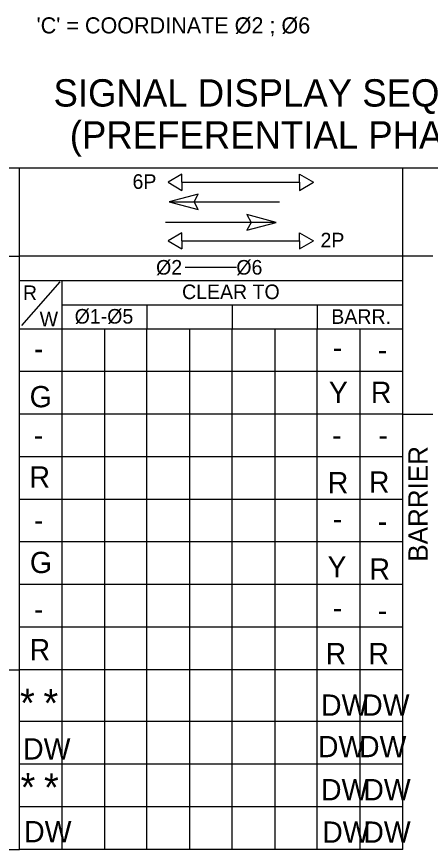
# Model space of a CAD drawing. Extents: x 0 to 3.01, y -0.05 to 1.83.
# Drawn here: x 2.5103 to 2.6475, y 1.2634 to 1.5395 of the extents above; entities that cross this region are included whole.
import ezdxf

# ---------------------------------------------------------------- set-up
doc = ezdxf.new("R2010")
doc.units = 0
for name, color, linetype in [('TR_TS_Border', 7, 'Continuous'), ('TR_TS_Phase1', 7, 'Continuous'), ('TR_TS_Phase2', 7, 'Continuous'), ('TR_TS_Phase3', 7, 'Continuous'), ('TR_TS_Phase4', 7, 'Continuous'), ('TR_TS_Phase5', 7, 'Continuous'), ('TR_TS_Phase6', 7, 'Continuous'), ('TR_TS_Phase7', 7, 'Continuous'), ('TR_TS_Phase8', 7, 'Continuous')]:
    doc.layers.add(name, color=color, linetype=linetype)

msp = doc.modelspace()

# ---------------------------------------------------------------- linework, layer by layer
at = {"layer": 'TR_TS_Border'}
for p, q in [((2.9074756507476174, 1.4891940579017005), (2.2983729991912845, 1.4891940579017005)), ((2.511179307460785, 1.4891941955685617), (2.511179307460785, 1.2634424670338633)), ((2.638251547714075, 1.4891941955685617), (2.638251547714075, 1.4077126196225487)), ((2.565108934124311, 1.467816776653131), (2.5605186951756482, 1.4651515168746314)), ((2.565108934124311, 1.4651515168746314), (2.565108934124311, 1.467816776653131)), ((2.604115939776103, 1.4651515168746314), (2.604115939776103, 1.467816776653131)), ((2.604115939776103, 1.467816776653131), (2.60870600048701, 1.4651515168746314)), ((2.5605186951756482, 1.4651515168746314), (2.565108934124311, 1.4624862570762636)), ((2.565108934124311, 1.4651515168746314), (2.565108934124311, 1.4624862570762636)), ((2.565108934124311, 1.4651515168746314), (2.604002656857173, 1.4651515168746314)), ((2.604115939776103, 1.4651515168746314), (2.604115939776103, 1.4624862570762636)), ((2.604115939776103, 1.4624862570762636), (2.60870600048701, 1.4651515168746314)), ((2.506117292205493, 1.4601230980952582), (2.511179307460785, 1.4601230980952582)), ((2.638251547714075, 1.4601230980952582), (2.511179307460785, 1.4601230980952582)), ((2.6483222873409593, 1.4601230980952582), (2.638251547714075, 1.4601230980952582)), ((2.566202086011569, 1.4563796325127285), (2.583186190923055, 1.4563796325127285)), ((2.511179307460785, 1.4520558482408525), (2.638251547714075, 1.4520558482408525)), ((2.5253103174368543, 1.4520558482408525), (2.5253103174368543, 1.2634424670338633)), ((2.512022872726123, 1.4371341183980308), (2.5246774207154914, 1.4515814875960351)), ((2.5253103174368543, 1.4439888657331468), (2.638251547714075, 1.4439888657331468)), ((2.5535190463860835, 1.4439888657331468), (2.5535190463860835, 1.4359214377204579)), ((2.5817279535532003, 1.4439888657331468), (2.5817279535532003, 1.4359214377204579)), ((2.609989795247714, 1.4439888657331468), (2.609989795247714, 1.4359214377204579)), ((2.638251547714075, 1.4359214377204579), (2.511179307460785, 1.4359214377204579)), ((2.5393882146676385, 1.4359214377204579), (2.5393882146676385, 1.2634424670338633)), ((2.5535190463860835, 1.2634424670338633), (2.5535190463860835, 1.4359214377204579)), ((2.567650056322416, 1.4359214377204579), (2.567650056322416, 1.2634424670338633)), ((2.5817279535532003, 1.2634424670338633), (2.5817279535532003, 1.4359214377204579)), ((2.595858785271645, 1.4359214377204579), (2.595858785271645, 1.2634424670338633)), ((2.609989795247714, 1.2634424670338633), (2.609989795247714, 1.4359214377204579)), ((2.6241206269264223, 1.4359214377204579), (2.6241206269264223, 1.2634424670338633)), ((2.638251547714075, 1.4217904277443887), (2.511179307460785, 1.4217904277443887)), ((2.638251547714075, 1.4077126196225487), (2.511179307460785, 1.4077126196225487)), ((2.638251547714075, 1.4077126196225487), (2.638251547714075, 1.2634424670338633)), ((2.638251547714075, 1.4077126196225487), (2.6483222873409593, 1.4077126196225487)), ((2.638251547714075, 1.39358169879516), (2.511179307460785, 1.39358169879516)), ((2.638251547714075, 1.3794506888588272), (2.511179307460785, 1.3794506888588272)), ((2.638251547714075, 1.365372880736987), (2.511179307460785, 1.365372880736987)), ((2.638251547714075, 1.3512419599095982), (2.511179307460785, 1.3512419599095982)), ((2.638251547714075, 1.3371109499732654), (2.511179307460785, 1.3371109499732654)), ((2.506117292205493, 1.3229801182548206), (2.511179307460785, 1.3229801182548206)), ((2.638251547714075, 1.3229801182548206), (2.511179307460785, 1.3229801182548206)), ((2.638324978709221, 1.3058350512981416), (2.5112527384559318, 1.3058350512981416)), ((2.638324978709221, 1.2917041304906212), (2.5112527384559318, 1.2917041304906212)), ((2.638324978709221, 1.2775732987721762), (2.5112527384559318, 1.2775732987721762)), ((2.5061908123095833, 1.2634424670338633), (2.5112527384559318, 1.2634424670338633)), ((2.638324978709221, 1.2634424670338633), (2.5112527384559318, 1.2634424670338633))]:
    msp.add_line(p, q, dxfattribs=at)
at = {"layer": 'TR_TS_Phase2'}
for p, q in [((2.5963022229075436, 1.4712633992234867), (2.5596551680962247, 1.4712633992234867)), ((2.5866775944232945, 1.4738546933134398), (2.5880103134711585, 1.4712633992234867)), ((2.5963022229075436, 1.4712633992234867), (2.5866775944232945, 1.4738546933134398)), ((2.5880103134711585, 1.4712633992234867), (2.5866775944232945, 1.4686721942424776)), ((2.5866775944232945, 1.4686721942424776), (2.5963022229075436, 1.4712633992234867))]:
    msp.add_line(p, q, dxfattribs=at)
at = {"layer": 'TR_TS_Phase6'}
for p, q in [((2.565108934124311, 1.4872207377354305), (2.5605186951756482, 1.4845554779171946)), ((2.565108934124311, 1.4845554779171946), (2.565108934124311, 1.4872207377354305)), ((2.604115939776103, 1.4872207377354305), (2.60870600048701, 1.4845554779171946)), ((2.604115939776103, 1.4845554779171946), (2.604115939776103, 1.4872207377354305)), ((2.5605186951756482, 1.4845554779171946), (2.565108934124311, 1.4818902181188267)), ((2.565108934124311, 1.4845554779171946), (2.565108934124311, 1.4818902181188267)), ((2.565108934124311, 1.4845554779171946), (2.604115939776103, 1.4845554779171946)), ((2.604115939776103, 1.4818902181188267), (2.60870600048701, 1.4845554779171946)), ((2.604115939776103, 1.4845554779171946), (2.604115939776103, 1.4818902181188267)), ((2.570465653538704, 1.4806770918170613), (2.5608412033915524, 1.4780859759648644)), ((2.569132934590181, 1.4780859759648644), (2.570465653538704, 1.4806770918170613)), ((2.5608412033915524, 1.4780859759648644), (2.5974881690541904, 1.4780859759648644)), ((2.5608412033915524, 1.4780859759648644), (2.570465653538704, 1.4754946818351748)), ((2.570465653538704, 1.4754946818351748), (2.569132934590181, 1.4780859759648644))]:
    msp.add_line(p, q, dxfattribs=at)

# ---------------------------------------------------------------- texts
at = {"layer": 'TR_TS_Border'}
for s, height, p in [("'C' = COORDINATE Ø2 ; Ø6", 0.0053469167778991, (2.5169014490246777, 1.5339009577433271)), ('SIGNAL DISPLAY SEQUENCE', 0.00906283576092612, (2.522526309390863, 1.5096612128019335)), ('(PREFERENTIAL PHASING)', 0.00906283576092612, (2.527912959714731, 1.4957467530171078)), ('2P', 0.004840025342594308, (2.611054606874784, 1.462976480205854))]:
    msp.add_text(s, height=height, dxfattribs=at).set_placement(p)
for s, height, rotation, p in [('Ø2          Ø6', 0.0048400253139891, 360, (2.556538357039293, 1.4539533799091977)), ('R', 0.004840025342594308, 360, (2.5123772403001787, 1.445516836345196)), ('CLEAR TO', 0.004840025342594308, 360, (2.565147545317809, 1.445833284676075)), ('W', 0.004840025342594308, 360, (2.517924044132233, 1.4368168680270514)), ('Ø1-Ø5', 0.004840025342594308, 360, (2.5295400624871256, 1.4377132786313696)), ('BARR.', 0.004840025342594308, 360, (2.6146445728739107, 1.4376254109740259)), ('BARRIER', 0.006449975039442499, 89.99999722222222, (2.6466355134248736, 1.3587942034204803))]:
    msp.add_text(s, height=height, rotation=rotation, dxfattribs=at).set_placement(p)
at = {"layer": 'TR_TS_Phase1'}
for p in [(2.516020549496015, 1.4259156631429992), (2.615139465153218, 1.4263307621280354), (2.630069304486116, 1.4255008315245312)]:
    msp.add_text('-', height=0.007050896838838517, dxfattribs=at).set_placement(p)
at = {"layer": 'TR_TS_Phase2'}
for s, p in [('G', (2.5146087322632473, 1.4099803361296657)), ('Y', (2.6138253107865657, 1.4114134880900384)), ('R', (2.6277444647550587, 1.4114134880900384))]:
    msp.add_text(s, height=0.007050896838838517, rotation=360, dxfattribs=at).set_placement(p)
for s, height, p in [('*', 0.009384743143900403, (2.511423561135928, 1.307294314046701)), ('*', 0.009384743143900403, (2.519194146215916, 1.3072379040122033)), ('DW', 0.007050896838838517, (2.6112267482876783, 1.307732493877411)), ('DW', 0.007050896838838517, (2.6248564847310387, 1.3077502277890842))]:
    msp.add_text(s, height=height, dxfattribs=at).set_placement(p)
at = {"layer": 'TR_TS_Phase3'}
for p in [(2.516010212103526, 1.3972038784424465), (2.6149433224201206, 1.3972038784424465), (2.630282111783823, 1.3972038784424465)]:
    msp.add_text('-', height=0.007050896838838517, dxfattribs=at).set_placement(p)
at = {"layer": 'TR_TS_Phase4'}
for p in [(2.514555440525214, 1.383343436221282), (2.61347087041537, 1.3814795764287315), (2.627105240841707, 1.3816624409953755)]:
    msp.add_text('R', height=0.007050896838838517, rotation=360, dxfattribs=at).set_placement(p)
for p in [(2.5124467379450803, 1.2932169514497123), (2.61019853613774, 1.2939920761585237), (2.623827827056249, 1.2939920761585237)]:
    msp.add_text('DW', height=0.007050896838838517, dxfattribs=at).set_placement(p)
at = {"layer": 'TR_TS_Phase5'}
for p in [(2.516020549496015, 1.3690909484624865), (2.615139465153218, 1.3695061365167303), (2.630069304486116, 1.3686761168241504)]:
    msp.add_text('-', height=0.007050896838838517, dxfattribs=at).set_placement(p)
at = {"layer": 'TR_TS_Phase6'}
for s, height, p in [('6P', 0.004840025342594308, (2.548725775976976, 1.4823806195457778)), ('*', 0.009384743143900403, (2.511606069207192, 1.2793452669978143)), ('*', 0.009384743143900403, (2.519376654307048, 1.2792890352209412)), ('DW', 0.007050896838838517, (2.6112267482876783, 1.279697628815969)), ('DW', 0.007050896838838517, (2.625246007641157, 1.279697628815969))]:
    msp.add_text(s, height=height, dxfattribs=at).set_placement(p)
for s, p in [('G', (2.5146930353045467, 1.355024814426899)), ('Y', (2.6133771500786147, 1.3535713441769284)), ('R', (2.6272963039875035, 1.3528246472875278))]:
    msp.add_text(s, height=0.007050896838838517, rotation=360, dxfattribs=at).set_placement(p)
at = {"layer": 'TR_TS_Phase7'}
for p in [(2.516020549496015, 1.339564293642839), (2.615139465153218, 1.3399794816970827), (2.630069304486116, 1.3391494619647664)]:
    msp.add_text('-', height=0.007050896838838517, dxfattribs=at).set_placement(p)
at = {"layer": 'TR_TS_Phase8'}
for p in [(2.514593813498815, 1.326112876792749), (2.612732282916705, 1.3248169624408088), (2.6269229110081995, 1.3248169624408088)]:
    msp.add_text('R', height=0.007050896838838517, rotation=360, dxfattribs=at).set_placement(p)
for p in [(2.512779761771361, 1.2657843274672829), (2.611616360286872, 1.265629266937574), (2.625245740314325, 1.265629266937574)]:
    msp.add_text('DW', height=0.007050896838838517, dxfattribs=at).set_placement(p)

doc.saveas('drawing.dxf')
